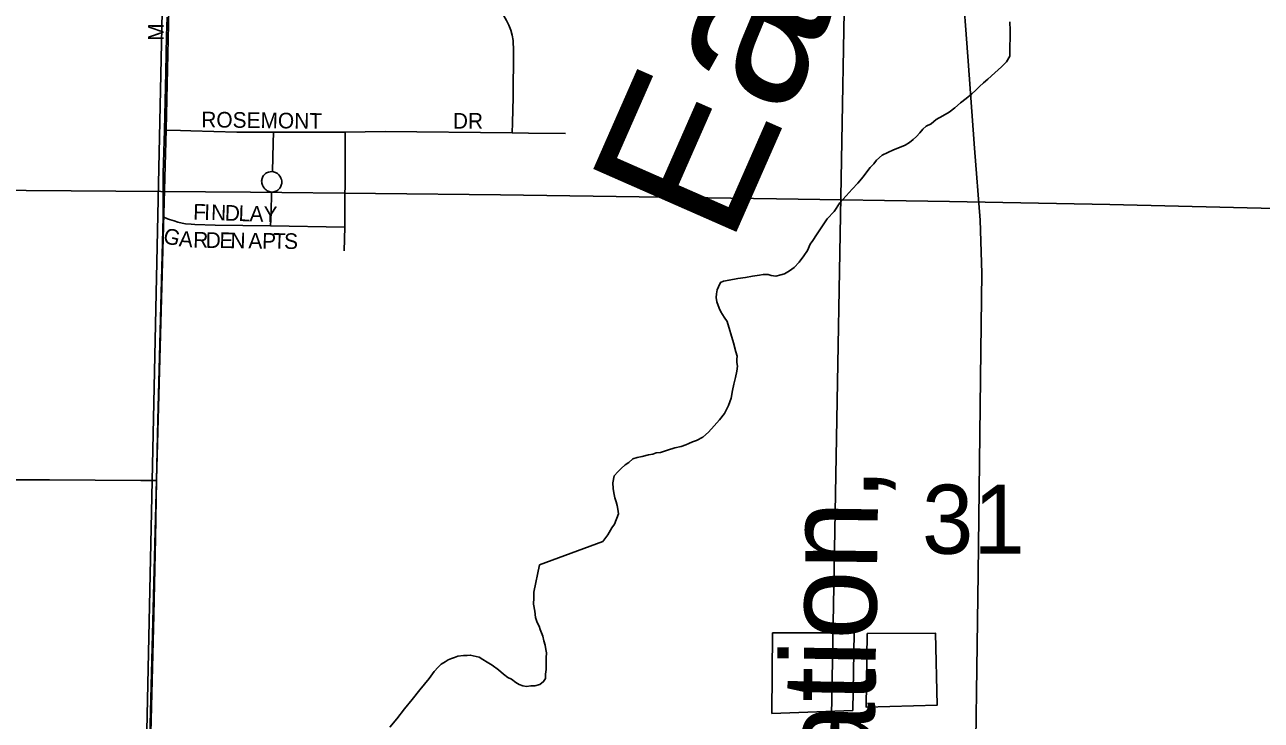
# Model space of a CAD drawing. Extents: x 0 to 68, y 0 to 52.9.
# Drawn here: x 43.81 to 44.601, y 35.667 to 36.112 of the extents above; entities that cross this region are included whole.
import ezdxf

# ---------------------------------------------------------------- set-up
doc = ezdxf.new("R2010")
doc.units = 0
for name, color, linetype in [('Default', 7, 'Continuous'), ('GM_X_Minor_Lake', 7, 'Continuous'), ('GM_X_Minor_River', 7, 'Continuous'), ('GM_X_Minor_River_Text', 7, 'Continuous'), ('GM_X_Township', 7, 'Continuous'), ('GM_X_Township_Road', 7, 'Continuous')]:
    doc.layers.add(name, color=color, linetype=linetype)

msp = doc.modelspace()

# ---------------------------------------------------------------- linework, layer by layer
at = {"layer": 'Default'}
for points in [[(44.41519, 35.42702), (44.41987, 35.76131), (44.42175, 35.90384), (44.42229, 35.95354), (44.42135, 35.98739), (44.41759, 36.0336), (44.41342, 36.09204), (44.4098, 36.14066), (44.40886, 36.17452), (44.40966, 36.19923), (44.41665, 36.28158), (44.42001, 36.32577), (44.42363, 36.36983), (44.42484, 36.3916), (44.42618, 36.4996), (44.42632, 36.55253), (44.42538, 36.58813), (44.4239, 36.60626), (44.42162, 36.62278), (44.41853, 36.63944), (44.41396, 36.65784), (44.39609, 36.71722)], [(44.12183, 36.04326), (44.12201, 36.0496), (44.1225, 36.06608), (44.12277, 36.09574), (44.12242, 36.10242), (44.12187, 36.10575), (44.121, 36.10903), (44.11981, 36.11221), (44.11828, 36.11524), (44.11647, 36.1181), (44.11443, 36.12078), (44.1055, 36.13055), (44.08183, 36.15547)], [(43.9003, 36.08204), (43.90082, 36.10547), (43.90113, 36.11729)], [(43.89948, 36.04504), (43.9003, 36.08204)], [(43.89867, 36.01733), (43.89948, 36.04504)], [(43.89948, 36.04504), (43.90979, 36.04476), (43.91632, 36.04458), (43.94578, 36.04377), (43.96924, 36.04369)], [(43.96848, 36.01854), (43.96901, 36.03675), (43.96924, 36.04369)], [(43.96924, 36.04369), (43.98505, 36.04364), (44.01502, 36.04364)], [(44.01488, 35.98291), (44.0151, 36.03055), (44.01502, 36.04364)], [(44.01502, 36.04364), (44.04062, 36.0441), (44.12183, 36.04326)], [(44.12183, 36.04326), (44.13223, 36.04315), (44.15609, 36.04298)], [(43.89854, 35.98957), (43.89867, 36.01733)], [(43.9679, 36.00529), (43.96647, 36.00571), (43.96521, 36.00629), (43.96449, 36.00678), (43.96389, 36.00733), (43.96334, 36.00797), (43.96295, 36.00842), (43.96262, 36.0089), (43.96231, 36.00943), (43.96211, 36.0099), (43.96192, 36.01047), (43.96178, 36.01107), (43.96168, 36.01171), (43.96163, 36.01238), (43.96168, 36.01294), (43.96177, 36.01351), (43.96211, 36.01468), (43.96242, 36.01538), (43.96286, 36.01602), (43.96325, 36.01648), (43.96366, 36.01689), (43.96414, 36.01726), (43.96479, 36.01762), (43.96535, 36.01788), (43.96606, 36.01809), (43.96699, 36.01829), (43.96848, 36.01854)], [(43.9679, 36.00529), (43.96933, 36.00546), (43.97014, 36.0057), (43.97075, 36.00596), (43.97128, 36.00622), (43.97193, 36.00663), (43.97241, 36.00705), (43.97276, 36.00747), (43.97316, 36.00795), (43.9736, 36.00856), (43.97392, 36.00919), (43.97417, 36.00976), (43.97435, 36.01036), (43.97444, 36.01091), (43.97453, 36.01192), (43.97445, 36.0127), (43.97427, 36.01351), (43.97396, 36.01428), (43.97369, 36.01495), (43.97318, 36.01569), (43.97267, 36.01636), (43.97222, 36.01684), (43.97181, 36.01722), (43.97138, 36.01753), (43.97092, 36.01779), (43.97044, 36.01803), (43.96991, 36.01821), (43.96923, 36.0184), (43.96848, 36.01854)], [(43.96737, 35.98386), (43.96761, 35.99218), (43.9679, 36.00529)], [(43.89443, 35.82078), (43.89528, 35.85945), (43.89854, 35.98957)], [(43.89854, 35.98957), (43.90138, 35.98838), (43.90273, 35.98781), (43.90568, 35.98693), (43.90802, 35.98622), (43.91087, 35.98556), (43.913, 35.98517), (43.91657, 35.98484), (43.91879, 35.98473), (43.93192, 35.98422), (43.96737, 35.98386)], [(43.96737, 35.98386), (44.01488, 35.98291)], [(44.01451, 35.96785), (44.01488, 35.98291)], [(43.80144, 35.8214), (43.822, 35.82128), (43.82598, 35.82125)], [(43.88793, 35.52467), (43.88887, 35.57152), (43.88935, 35.59375), (43.89094, 35.64952), (43.89084, 35.65938), (43.89262, 35.73479), (43.89362, 35.78401), (43.89443, 35.82078)]]:
    msp.add_lwpolyline(points, dxfattribs=at)
for points in [[(43.11555, 36.67874), (44.34414, 36.66665), (44.32023, 35.33817), (43.69327, 35.3509), (43.1026, 35.34663), (43.11455, 36.64024)], [(44.34414, 36.66665), (45.68961, 36.62483), (45.66716, 35.30232), (44.32023, 35.33817)], [(42.83718, 36.36115), (43.90273, 36.34073), (43.8802, 35.29067), (42.82102, 35.30893)], [(43.90273, 36.34073), (44.95281, 36.32851), (44.93588, 35.27966), (44.90228, 35.2801), (43.8802, 35.29067)]]:
    msp.add_lwpolyline(points, close=True, dxfattribs=at)
at = {"layer": 'GM_X_Minor_Lake'}
for points in [[(44.28843, 35.72349), (44.34058, 35.72352), (44.33978, 35.6738), (44.28807, 35.67186), (44.28843, 35.72349)], [(44.28843, 35.72349), (44.28807, 35.67186), (44.33978, 35.6738)], [(44.33978, 35.6738), (44.34058, 35.72352), (44.28843, 35.72349)], [(44.34887, 35.72307), (44.39272, 35.72313), (44.39384, 35.67719), (44.34837, 35.67586), (44.34887, 35.72307)], [(44.34887, 35.72307), (44.34837, 35.67586), (44.39384, 35.67719)], [(44.39384, 35.67719), (44.39272, 35.72313), (44.34887, 35.72307)]]:
    msp.add_lwpolyline(points, dxfattribs=at)
at = {"layer": 'GM_X_Minor_River'}
for points in [[(44.44023, 36.11436), (44.44051, 36.10874), (44.44041, 36.10392), (44.44031, 36.09871), (44.44023, 36.0947), (44.44018, 36.09229), (44.4381, 36.08873), (44.43483, 36.08558), (44.43073, 36.08165), (44.42624, 36.07773), (44.42338, 36.07538), (44.42093, 36.07302), (44.41847, 36.07066), (44.41601, 36.06831), (44.41234, 36.06517), (44.40867, 36.06244), (44.405, 36.0593), (44.40133, 36.05657), (44.39727, 36.05424), (44.39321, 36.05192), (44.38994, 36.04917), (44.3867, 36.04763), (44.38465, 36.04567), (44.3826, 36.0433), (44.38055, 36.04094), (44.3785, 36.03897), (44.37605, 36.03702), (44.37321, 36.03547), (44.36957, 36.03394)], [(44.36957, 36.03394), (44.36592, 36.03241), (44.35863, 36.02894), (44.35496, 36.02581), (44.3533, 36.02343), (44.35085, 36.02107), (44.34878, 36.01831), (44.34631, 36.01515), (44.34302, 36.0112), (44.33933, 36.00726), (44.33563, 36.00293), (44.33153, 35.99859), (44.3278, 35.99305), (44.32329, 35.98833), (44.31998, 35.98318), (44.31666, 35.97803), (44.31418, 35.97447), (44.31253, 35.9721), (44.31084, 35.96812), (44.30836, 35.96456), (44.30547, 35.9606), (44.30219, 35.95706), (44.29934, 35.95511), (44.29609, 35.95317), (44.29367, 35.95242), (44.29044, 35.95168), (44.28764, 35.95214), (44.28565, 35.95258), (44.28244, 35.95264), (44.28002, 35.95229), (44.27559, 35.95158), (44.27117, 35.95086), (44.26633, 35.95016), (44.26069, 35.94907), (44.25707, 35.94834), (44.25505, 35.94758), (44.25378, 35.94479), (44.25294, 35.9428), (44.25249, 35.94041), (44.25244, 35.938), (44.25279, 35.93519), (44.25431, 35.93114), (44.25546, 35.92871), (44.25741, 35.92546), (44.25936, 35.92261), (44.26349, 35.90889), (44.26498, 35.90324), (44.26573, 35.90042), (44.26569, 35.89842), (44.26565, 35.89641), (44.266, 35.894), (44.26553, 35.8908), (44.26465, 35.8868), (44.26376, 35.88241), (44.26287, 35.87841), (44.26197, 35.87362), (44.26027, 35.86884), (44.25776, 35.86367), (44.25447, 35.85972), (44.25118, 35.85578), (44.24749, 35.85184), (44.24381, 35.84871), (44.23975, 35.84638), (44.23733, 35.84563), (44.2349, 35.84447), (44.23287, 35.84371), (44.23004, 35.84256), (44.22601, 35.84184), (44.22117, 35.84034), (44.21672, 35.83882), (44.21391, 35.83848), (44.21188, 35.83771), (44.20907, 35.83737), (44.20503, 35.83625), (44.2018, 35.83551), (44.19898, 35.83476), (44.19653, 35.83241), (44.19409, 35.83085), (44.19163, 35.82849), (44.18958, 35.82653), (44.18712, 35.82377), (44.18623, 35.81937), (44.18656, 35.81576), (44.1869, 35.81294), (44.18764, 35.80972), (44.18839, 35.8073), (44.18915, 35.80487), (44.1895, 35.80246), (44.18984, 35.79964), (44.1873, 35.79287), (44.18564, 35.7905), (44.18315, 35.78614), (44.17985, 35.78179), (44.1394, 35.76684)], [(44.1394, 35.76684), (44.13569, 35.7494), (44.13565, 35.74578), (44.13561, 35.74176), (44.13637, 35.73733), (44.13674, 35.73331), (44.13791, 35.73008), (44.13909, 35.72766), (44.13988, 35.72564), (44.14144, 35.7212), (44.14222, 35.71838), (44.14299, 35.71556), (44.14337, 35.71275), (44.14375, 35.71073), (44.14372, 35.70752), (44.1437, 35.70551), (44.14367, 35.7027), (44.14364, 35.69988), (44.14322, 35.69707), (44.14319, 35.69426), (44.14196, 35.69226), (44.13953, 35.69028), (44.13631, 35.68951), (44.1339, 35.68953), (44.13108, 35.68916), (44.12867, 35.68959), (44.12627, 35.69042), (44.12427, 35.69164), (44.12148, 35.69368), (44.11908, 35.69491), (44.11628, 35.69695), (44.1131, 35.6998), (44.1091, 35.70265), (44.10591, 35.70469), (44.10311, 35.70633), (44.10072, 35.70796), (44.0951, 35.70923), (44.09309, 35.70885), (44.09068, 35.70887), (44.08706, 35.70851), (44.08504, 35.70772), (44.08302, 35.70694), (44.081, 35.70616), (44.07898, 35.70497), (44.07655, 35.70339), (44.07453, 35.7014), (44.07209, 35.69861), (44.06883, 35.69423), (44.06273, 35.68706), (44.05784, 35.68068), (44.05296, 35.6747), (44.04807, 35.66832), (44.0436, 35.66314)]]:
    msp.add_lwpolyline(points, dxfattribs=at)
at = {"layer": 'GM_X_Township'}
msp.add_lwpolyline([(43.88559, 35.48361), (43.89433, 35.82141), (43.90046, 36.04535), (43.90532, 36.25787), (43.90489, 36.28618), (43.90616, 36.33667), (43.90637, 36.38843), (43.90806, 36.45476), (43.90849, 36.48223), (43.90912, 36.52786), (43.91165, 36.66349), (43.91229, 36.75095)], dxfattribs=at)
at = {"layer": 'GM_X_Township_Road'}
for points in [[(43.1128, 36.01316), (43.12152, 36.01311), (43.3349, 36.01179), (43.63443, 36.00853), (43.68363, 36.00792), (43.75337, 36.00694), (43.95444, 36.00529), (44.11447, 36.00356), (44.18832, 36.00256), (44.29089, 36.00109), (44.40167, 35.99944), (44.50423, 35.99741), (44.87343, 35.98842), (44.98829, 35.98527), (45.008, 35.98469)], [(43.82598, 35.82125), (43.88429, 35.82085), (43.89443, 35.82078)]]:
    msp.add_lwpolyline(points, dxfattribs=at)

# ---------------------------------------------------------------- texts
at = {"layer": 'Default'}
for s, height, rotation, p in [('M', 0.01, 89.92714, (43.89902, 36.10218)), ('ROSEMONT', 0.01, 359.24562, (43.92294, 36.04686)), ('DR', 0.01, 0.00001, (44.08394, 36.04598)), ('F', 0.01, 358.0326, (43.91768, 35.9879)), ('I', 0.01, 357.98891, (43.92472, 35.98766)), ('N', 0.01, 358.04498, (43.92913, 35.98751)), ('D', 0.01, 358.0326, (43.93792, 35.98721)), ('L', 0.01, 358.00529, (43.94671, 35.9869)), ('A', 0.01, 358.03368, (43.95376, 35.98666)), ('Y', 0.01, 358.74287, (43.96269, 35.98635)), ('G', 0.01, 345.57681, (43.89799, 35.97319)), ('A', 0.01, 355.49987, (43.90838, 35.97069)), ('R', 0.01, 358.5212, (43.91772, 35.96997)), ('D', 0.01, 359.06943, (43.92575, 35.96976)), ('E', 0.01, 359.25456, (43.93458, 35.96962)), ('N', 0.01, 359.24952, (43.94162, 35.96953)), ('A', 0.01, 359.24952, (43.95306, 35.96938)), ('P', 0.01, 359.25456, (43.96186, 35.96926)), ('T', 0.01, 359.25456, (43.96889, 35.96917)), ('S', 0.01, 359.25456, (43.97593, 35.96908)), ('Transportation,', 0.0598, 89.17029, (44.34844, 35.29203)), ('31', 0.0442, 0.00001, (44.38402, 35.774))]:
    msp.add_text(s, height=height, rotation=rotation, dxfattribs=at).set_placement(p)
at = {"layer": 'GM_X_Minor_River_Text'}
msp.add_text('Eagle', height=0.100043, rotation=66.26026, dxfattribs=at).set_placement((44.26093, 35.96989))

doc.saveas('drawing.dxf')
